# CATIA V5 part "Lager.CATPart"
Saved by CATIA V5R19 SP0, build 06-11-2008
Part number: lager
Bounding box of the stored display mesh (mm): x 0 to 20, y -15 to 15, z -15 to 15
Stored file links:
  H:\Bachelorarbeit_Hahn\Neue Vereinfachung\Lager.CATPart
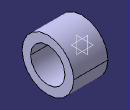
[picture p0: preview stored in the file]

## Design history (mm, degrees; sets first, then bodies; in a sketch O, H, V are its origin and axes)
Body1 (main body)
  Sketch1 on yz-plane, origin (0, 0, 0), H (0, 1, 0), V (0, 0, 1)
    circle A1 centre (0, 0) radius 10
    circle A2 centre (0, 0) radius 15
    radius A1 = 10
    radius A2 = 15
  Pad1: profile Sketch1, direction (1, 0, 0), length 20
